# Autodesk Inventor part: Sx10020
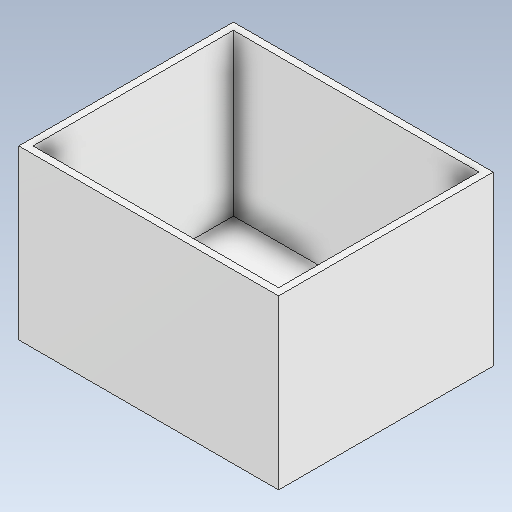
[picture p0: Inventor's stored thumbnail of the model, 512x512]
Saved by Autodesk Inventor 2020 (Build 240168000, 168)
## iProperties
Created: 2021-02
Part Number: Sx10020
Material: Generico
Document SubType Name: Modeling
Designer: zambolin
Density: 1 g/cm^3
Appearance: Default
Author: zambolin
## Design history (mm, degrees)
feature "Solido2"
node "Solido1"
